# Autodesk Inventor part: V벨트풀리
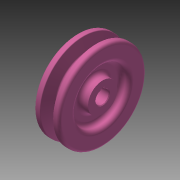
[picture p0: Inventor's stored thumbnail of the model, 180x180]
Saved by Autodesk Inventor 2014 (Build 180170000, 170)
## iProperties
Created: 2015-11
Part Number: V벨트풀리
Material: 강철, 탄소
Document SubType Name: Modeling
Designer: mduedu
Density: 1 g/cm^3
Appearance: 분홍색
Author: mduedu
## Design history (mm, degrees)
sketch "스케치1"
  geometry: L1 (-9.5, 0)-(9.5, 0); L2 (0, 0)-(0, 32.7); L3 (-4.825, 32.7)-(-9.5, 32.7); L4 (-9.5, 32.7)-(-9.5, 0); L5 (0, 23.7)-(-2.074, 23.7); L6 (-2.074, 23.7)-(-4.825, 32.7); L7 (4.825, 32.7)-(9.5, 32.7); L8 (9.5, 32.7)-(9.5, 0); L9 (0, 23.7)-(2.074, 23.7); L10 (2.074, 23.7)-(4.825, 32.7); L11 (-9.5, 30)-(9.5, 30); 3 further points
  constraints: 22 end point, 7 point on line, 4 perpendicular, 3 symmetric about line, 1 coincident, 1 horizontal, 1 horizontal alignment, 1 midpoint, 1 vertical
  dimensions: "d0" = 19 distance of L1.start L1.end; "d2" = 65.4 diameter of L2.end L1 (derived); "d3" = 34 deg angle of L10 L6; "d4" = 6.3 distance between parallel lines of L11 L9; "d5" = 2.7 distance between parallel lines of L7 L11; "d6" = 8 distance of point (4, 30) point (-4, 30); "d7" = 60 diameter of L11 L1
revolve "회전1" sketch "스케치1" stored, may be unused: angle "d8" = 90 deg
sketch "스케치2"
  geometry: C1 r 20 at (0, 0); C2 r 11 at (0, 0); 1 further point
  constraints: 2 centre point, 2 coincident
  dimensions: "d9" = 40 diameter of C1; "d10" = 22 diameter of C2
extrude "돌출1" cut sketch "스케치2" distance "d11" = 6; taper "d12" = 0 deg
fillet "모깎기1" dims "d13" = 3
fillet "모깎기2" dims "d14" = 3
fillet "모깎기3" dims "d15" = 1, "d16" = 0.5, "d17" = 2
hole "구멍1" diameter "d20" = 10; stored, may be unused: countersink angle "d24" = 90 deg, drill point angle "d26" = 118 deg; dims "d18" = 10, "d19" = 10, "d21" = 6, "d22" = 4, "d23" = 2, "d25" = 8
sketch "스케치3"
  geometry: L1 (-1.5, 0)-(1.5, 0); L2 (1.5, 0)-(1.5, 6.4); L3 (1.5, 6.4)-(-1.5, 6.4); L4 (-1.5, 6.4)-(-1.5, 0); 2 further points
  constraints: 8 end point, 2 parallel, 1 coincident, 1 horizontal, 1 midpoint, 1 perpendicular
  dimensions: "d27" = 3 distance of L2.end L3.end; "d29" = 6.4 distance of L3.end L1.start
extrude "돌출2" cut sketch "스케치3" stored distance "d30" = 6; taper "d31" = 0 deg
chamfer "모따기1" distance "d32" = 0.5; stored, may be unused: second distance "d33" = 2, angle "d34" = 45 deg
node "솔리드1"
mirror "대칭1"
